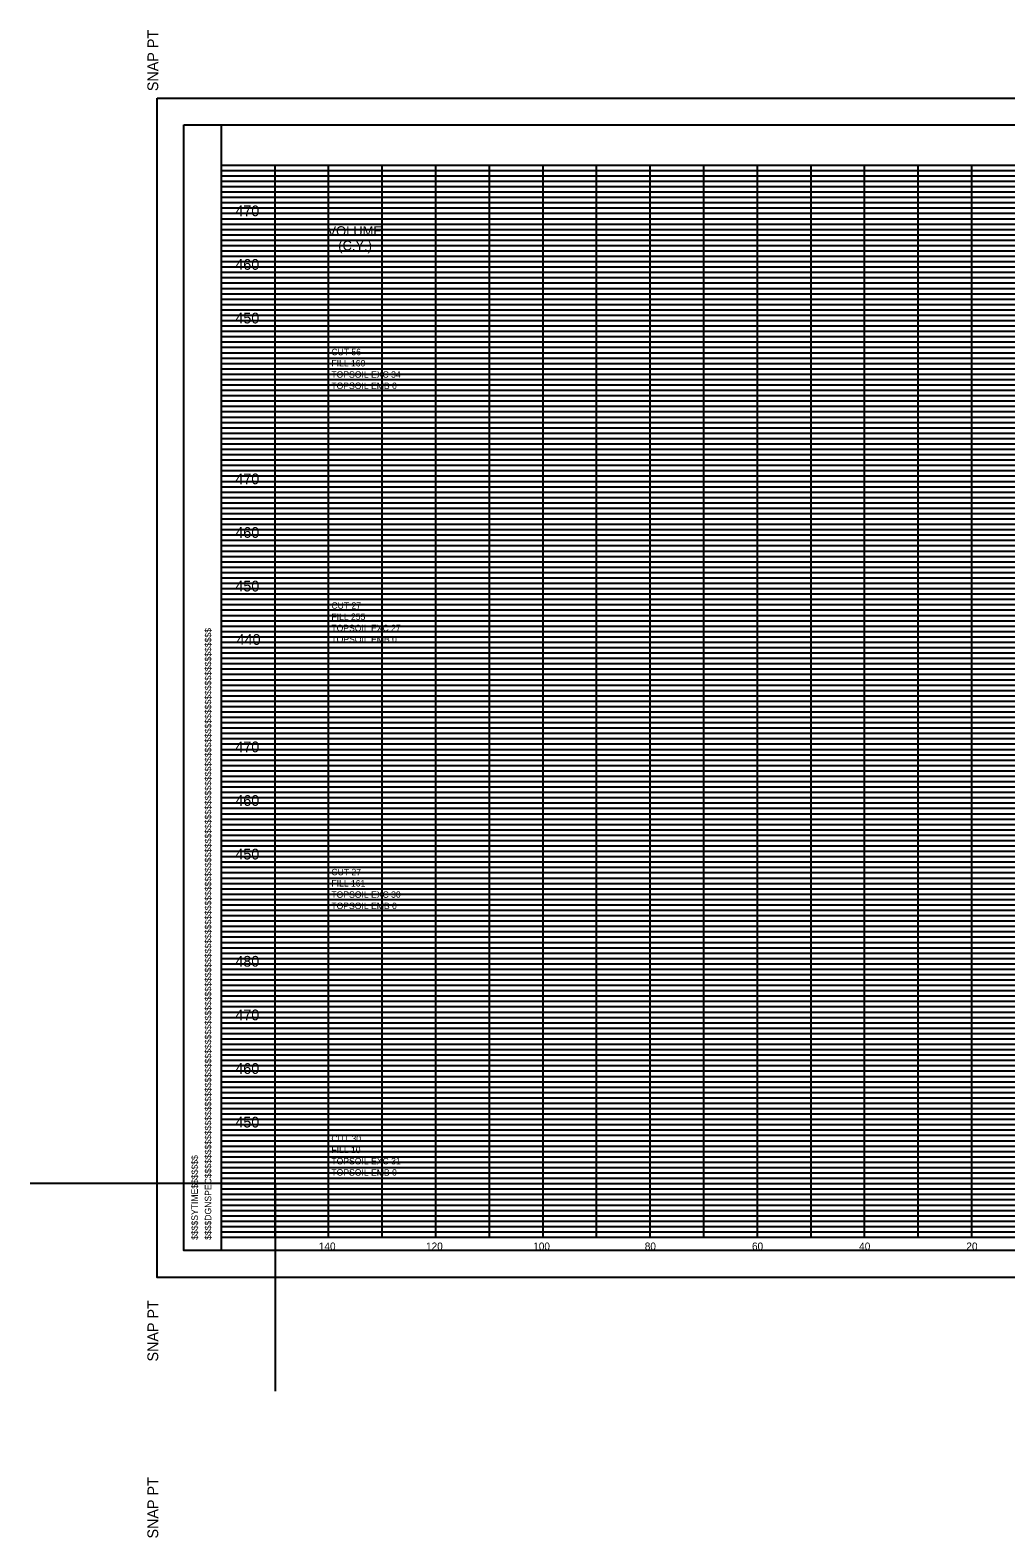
# Model space of a CAD drawing. Extents: x 37 to 1710, y 707 to 2305.
# Drawn here: x 964.3 to 1146.3, y 1213.9 to 1495.2 of the extents above; entities that cross this region are included whole.
import ezdxf

# ---------------------------------------------------------------- set-up
doc = ezdxf.new("R2010")
doc.units = 0
for name, color, linetype in [('DESIGN - SCRATCH - User 1', 7, 'Continuous'), ('DESIGN - SHEET - Corner Text', 7, 'Continuous'), ('DESIGN - SHEET - Light Grid', 7, 'Continuous'), ('DESIGN - SHEET - Linework', 7, 'Continuous'), ('DESIGN - SHEET - Plot Shape', 7, 'Continuous'), ('DESIGN - TYPICAL - Text', 7, 'Continuous')]:
    doc.layers.add(name, color=color, linetype=linetype)

msp = doc.modelspace()

# ---------------------------------------------------------------- linework, layer by layer
at = {"layer": 'DESIGN - SCRATCH - User 1'}
for p, q in [((1010, 1280), (964.31, 1280)), ((1010, 1280), (1010, 1241.3)), ((1000, 1270), (1000, 1270))]:
    msp.add_line(p, q, dxfattribs=at)
at = {"layer": 'DESIGN - SHEET - Light Grid'}
for p, q in [((1000, 1469), (1280, 1469)), ((1000, 1468), (1280, 1468)), ((1000, 1467), (1320, 1467)), ((1000, 1466), (1320, 1466)), ((1000, 1465), (1320, 1465)), ((1000, 1464), (1320, 1464)), ((1000, 1463), (1320, 1463)), ((1000, 1462), (1320, 1462)), ((1000, 1461), (1320, 1461)), ((1000, 1459), (1320, 1459)), ((1000, 1458), (1320, 1458)), ((1000, 1457), (1320, 1457)), ((1000, 1456), (1320, 1456)), ((1000, 1455), (1320, 1455)), ((1000, 1454), (1320, 1454)), ((1000, 1453), (1320, 1453)), ((1000, 1452), (1320, 1452)), ((1000, 1451), (1320, 1451)), ((1000, 1449), (1320, 1449)), ((1000, 1448), (1320, 1448)), ((1000, 1447), (1320, 1447)), ((1000, 1446), (1320, 1446)), ((1000, 1445), (1320, 1445)), ((1000, 1444), (1320, 1444)), ((1000, 1443), (1320, 1443)), ((1000, 1442), (1320, 1442)), ((1000, 1441), (1320, 1441)), ((1000, 1439), (1320, 1439)), ((1000, 1438), (1320, 1438)), ((1000, 1437), (1320, 1437)), ((1000, 1436), (1320, 1436)), ((1000, 1435), (1320, 1435)), ((1000, 1434), (1320, 1434)), ((1000, 1433), (1320, 1433)), ((1000, 1432), (1320, 1432)), ((1000, 1431), (1320, 1431)), ((1000, 1429), (1320, 1429)), ((1000, 1428), (1320, 1428)), ((1000, 1427), (1320, 1427)), ((1000, 1426), (1320, 1426)), ((1000, 1425), (1320, 1425)), ((1000, 1424), (1320, 1424)), ((1000, 1423), (1320, 1423)), ((1000, 1422), (1320, 1422)), ((1000, 1421), (1320, 1421)), ((1000, 1419), (1320, 1419)), ((1000, 1418), (1320, 1418)), ((1000, 1417), (1320, 1417)), ((1000, 1416), (1320, 1416)), ((1000, 1415), (1320, 1415)), ((1000, 1414), (1320, 1414)), ((1000, 1413), (1320, 1413)), ((1000, 1412), (1320, 1412)), ((1000, 1411), (1320, 1411)), ((1000, 1409), (1320, 1409)), ((1000, 1408), (1320, 1408)), ((1000, 1407), (1320, 1407)), ((1000, 1406), (1320, 1406)), ((1000, 1405), (1320, 1405)), ((1000, 1404), (1320, 1404)), ((1000, 1403), (1320, 1403)), ((1000, 1402), (1320, 1402)), ((1000, 1401), (1320, 1401)), ((1000, 1399), (1320, 1399)), ((1000, 1398), (1320, 1398)), ((1000, 1397), (1320, 1397)), ((1000, 1396), (1320, 1396)), ((1000, 1395), (1320, 1395)), ((1000, 1394), (1320, 1394)), ((1000, 1393), (1320, 1393)), ((1000, 1392), (1320, 1392)), ((1000, 1391), (1320, 1391)), ((1000, 1389), (1320, 1389)), ((1000, 1388), (1320, 1388)), ((1000, 1387), (1320, 1387)), ((1000, 1386), (1320, 1386)), ((1000, 1385), (1320, 1385)), ((1000, 1384), (1320, 1384)), ((1000, 1383), (1320, 1383)), ((1000, 1382), (1320, 1382)), ((1000, 1381), (1320, 1381)), ((1000, 1379), (1320, 1379)), ((1000, 1378), (1320, 1378)), ((1000, 1377), (1320, 1377)), ((1000, 1376), (1320, 1376)), ((1000, 1375), (1320, 1375)), ((1000, 1374), (1320, 1374)), ((1000, 1373), (1320, 1373)), ((1000, 1372), (1320, 1372)), ((1000, 1371), (1320, 1371)), ((1000, 1369), (1320, 1369)), ((1000, 1368), (1320, 1368)), ((1000, 1367), (1320, 1367)), ((1000, 1366), (1320, 1366)), ((1000, 1365), (1320, 1365)), ((1000, 1364), (1320, 1364)), ((1000, 1363), (1320, 1363)), ((1000, 1362), (1320, 1362)), ((1000, 1361), (1320, 1361)), ((1000, 1359), (1320, 1359)), ((1000, 1358), (1320, 1358)), ((1000, 1357), (1320, 1357)), ((1000, 1356), (1320, 1356)), ((1000, 1355), (1320, 1355)), ((1000, 1354), (1320, 1354)), ((1000, 1353), (1320, 1353)), ((1000, 1352), (1320, 1352)), ((1000, 1351), (1320, 1351)), ((1000, 1349), (1320, 1349)), ((1000, 1348), (1320, 1348)), ((1000, 1347), (1320, 1347)), ((1000, 1346), (1320, 1346)), ((1000, 1345), (1320, 1345)), ((1000, 1344), (1320, 1344)), ((1000, 1343), (1320, 1343)), ((1000, 1342), (1320, 1342)), ((1000, 1341), (1320, 1341)), ((1000, 1339), (1320, 1339)), ((1000, 1338), (1320, 1338)), ((1000, 1337), (1320, 1337)), ((1000, 1336), (1320, 1336)), ((1000, 1335), (1320, 1335)), ((1000, 1334), (1320, 1334)), ((1000, 1333), (1320, 1333)), ((1000, 1332), (1320, 1332)), ((1000, 1331), (1320, 1331)), ((1000, 1329), (1320, 1329)), ((1000, 1328), (1320, 1328)), ((1000, 1327), (1320, 1327)), ((1000, 1326), (1320, 1326)), ((1000, 1325), (1320, 1325)), ((1000, 1324), (1320, 1324)), ((1000, 1323), (1320, 1323)), ((1000, 1322), (1320, 1322)), ((1000, 1321), (1320, 1321)), ((1000, 1319), (1320, 1319)), ((1000, 1318), (1320, 1318)), ((1000, 1317), (1320, 1317)), ((1000, 1316), (1320, 1316)), ((1000, 1315), (1320, 1315)), ((1000, 1314), (1320, 1314)), ((1000, 1313), (1320, 1313)), ((1000, 1312), (1320, 1312)), ((1000, 1311), (1320, 1311)), ((1000, 1309), (1320, 1309)), ((1000, 1308), (1320, 1308)), ((1000, 1307), (1320, 1307)), ((1000, 1306), (1320, 1306)), ((1000, 1305), (1320, 1305)), ((1000, 1304), (1320, 1304)), ((1000, 1303), (1320, 1303)), ((1000, 1302), (1320, 1302)), ((1000, 1301), (1320, 1301)), ((1000, 1299), (1320, 1299)), ((1000, 1298), (1320, 1298)), ((1000, 1297), (1320, 1297)), ((1000, 1296), (1320, 1296)), ((1000, 1295), (1320, 1295)), ((1000, 1294), (1320, 1294)), ((1000, 1293), (1320, 1293)), ((1000, 1292), (1320, 1292)), ((1000, 1291), (1320, 1291)), ((1000, 1289), (1320, 1289)), ((1000, 1288), (1320, 1288)), ((1000, 1287), (1320, 1287)), ((1000, 1286), (1320, 1286)), ((1000, 1285), (1320, 1285)), ((1000, 1284), (1320, 1284)), ((1000, 1283), (1320, 1283)), ((1000, 1282), (1320, 1282)), ((1000, 1281), (1320, 1281)), ((1000, 1279), (1320, 1279)), ((1000, 1278), (1320, 1278)), ((1000, 1277), (1320, 1277)), ((1000, 1276), (1320, 1276)), ((1000, 1275), (1320, 1275)), ((1000, 1274), (1320, 1274)), ((1000, 1273), (1320, 1273)), ((1000, 1272), (1320, 1272)), ((1000, 1271), (1320, 1271))]:
    msp.add_line(p, q, dxfattribs=at)
at = {"layer": 'DESIGN - SHEET - Linework'}
for p, q in [((1000, 1470), (1320, 1470)), ((1010, 1270), (1010, 1470)), ((1020, 1270), (1020, 1470)), ((1030, 1270), (1030, 1470)), ((1040, 1270), (1040, 1470)), ((1050, 1270), (1050, 1470)), ((1060, 1270), (1060, 1470)), ((1070, 1270), (1070, 1470)), ((1080, 1270), (1080, 1470)), ((1090, 1270), (1090, 1470)), ((1100, 1270), (1100, 1470)), ((1110, 1270), (1110, 1470)), ((1120, 1270), (1120, 1470)), ((1130, 1270), (1130, 1470)), ((1140, 1270), (1140, 1470)), ((1000, 1460), (1320, 1460)), ((1000, 1450), (1320, 1450)), ((1000, 1440), (1320, 1440)), ((1000, 1430), (1320, 1430)), ((1000, 1420), (1320, 1420)), ((1000, 1410), (1320, 1410)), ((1000, 1400), (1320, 1400)), ((1000, 1390), (1320, 1390)), ((1000, 1380), (1320, 1380)), ((1000, 1370), (1320, 1370)), ((1000, 1360), (1320, 1360)), ((1000, 1350), (1320, 1350)), ((1000, 1340), (1320, 1340)), ((1000, 1330), (1320, 1330)), ((1000, 1320), (1320, 1320)), ((1000, 1310), (1320, 1310)), ((1000, 1300), (1320, 1300)), ((1000, 1290), (1320, 1290)), ((1000, 1280), (1320, 1280)), ((1000, 1270), (1320, 1270))]:
    msp.add_line(p, q, dxfattribs=at)
for points in [[(988, 1482.5), (1328, 1482.5), (1328, 1262.5), (988, 1262.5)], [(1000, 1477.5), (1320, 1477.5), (1320, 1267.5), (1000, 1267.5)]]:
    msp.add_lwpolyline(points, close=True, dxfattribs=at)
at = {"layer": 'DESIGN - SHEET - Plot Shape'}
msp.add_lwpolyline([(993, 1477.5), (1323, 1477.5), (1323, 1267.5), (993, 1267.5)], close=True, dxfattribs=at)

# ---------------------------------------------------------------- texts
at = {"layer": 'DESIGN - SHEET - Corner Text'}
for s, height, p in [('  SNAP PT', 2, (988.2, 1482.3)), ('$$$$DGNSPEC$$$$$$$$$$$$$$$$$$$$$$$$$$$$$$$$$$$$$$$$$$$$$$$$$$$$$$$$$$$$$$$$$$$$$$$$$$$$$$$$$$$$$$$$$$$$$$$$$$$$$$$$$$$$$$$$$$$', 1.2, (998.1, 1269.5)), ('$$$$SYTIME$$$$$$$', 1.2, (995.6, 1269.5)), ('SNAP PT  ', 2, (988.2, 1246.8)), ('  SNAP PT', 2, (988.2, 1212.3))]:
    msp.add_text(s, height=height, rotation=90, dxfattribs=at).set_placement(p)
at = {"layer": 'DESIGN - TYPICAL - Text'}
for s, height, p in [('     470     ', 2, (998.88, 1460.46)), ('VOLUME', 1.8, (1019.79, 1456.79)), ('   (C.Y.)', 1.8, (1019.79, 1454.09)), ('     460     ', 2, (998.88, 1450.46)), ('     450     ', 2, (998.88, 1440.46)), ('CUT 56', 1.2, (1020.51, 1434.53)), ('FILL 160', 1.2, (1020.51, 1432.43)), ('TOPSOIL EXC 34', 1.2, (1020.51, 1430.33)), ('TOPSOIL EMB 0', 1.2, (1020.51, 1428.23)), ('     470     ', 2, (998.88, 1410.46)), ('     460     ', 2, (998.88, 1400.46)), ('     450     ', 2, (998.88, 1390.46)), ('CUT 27', 1.2, (1020.51, 1387.24)), ('TOPSOIL EXC 27', 1.2, (1020.51, 1383.04)), ('FILL 255', 1.2, (1020.51, 1385.14)), ('440', 2, (1002.84, 1380.5)), ('TOPSOIL EMB 0', 1.2, (1020.51, 1380.94)), ('     470     ', 2, (998.88, 1360.46)), ('     460     ', 2, (998.88, 1350.46)), ('     450     ', 2, (998.88, 1340.46)), ('CUT 27', 1.2, (1020.51, 1337.51)), ('FILL 161', 1.2, (1020.51, 1335.41)), ('TOPSOIL EXC 30', 1.2, (1020.51, 1333.31)), ('TOPSOIL EMB 0', 1.2, (1020.51, 1331.21)), ('     480     ', 2, (998.88, 1320.46)), ('     470     ', 2, (998.88, 1310.46)), ('     460     ', 2, (998.88, 1300.46)), ('     450     ', 2, (998.88, 1290.46)), ('CUT 30', 1.2, (1020.51, 1287.78)), ('FILL 10', 1.2, (1020.51, 1285.68)), ('TOPSOIL EXC 31', 1.2, (1020.51, 1283.58)), ('TOPSOIL EMB 0', 1.2, (1020.51, 1281.48)), ('     140     ', 1.4, (1015.57, 1267.6)), ('     120     ', 1.4, (1035.57, 1267.6)), ('     100     ', 1.4, (1055.57, 1267.6)), ('     80     ', 1.4, (1076.38, 1267.6)), ('     60     ', 1.4, (1096.38, 1267.6)), ('     40     ', 1.4, (1116.38, 1267.6)), ('     20     ', 1.4, (1136.38, 1267.6))]:
    msp.add_text(s, height=height, dxfattribs=at).set_placement(p)

doc.saveas('drawing.dxf')
